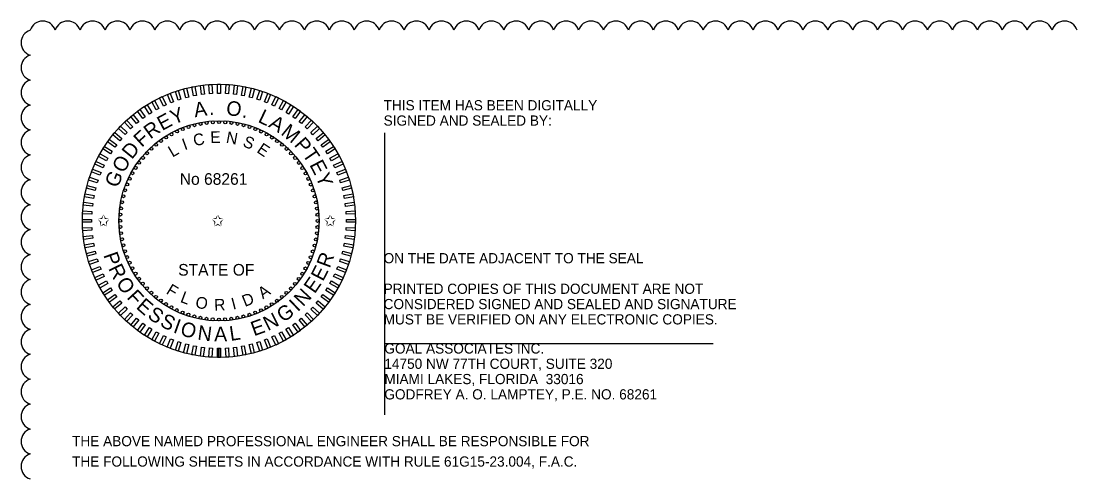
# Model space of a CAD drawing. Extents: x -811 to 10319, y -2309 to 9962.
# Drawn here: x -810.85 to -803.6, y -2238.16 to -2235.02 of the extents above; entities that cross this region are included whole.
import ezdxf

# ---------------------------------------------------------------- set-up
doc = ezdxf.new("R2010")
doc.units = 0
for name, color, linetype in [('AdhocPoint_dp', 7, 'Continuous'), ('PlotBorder_dp', 7, 'Continuous'), ('TextMinor', 7, 'Continuous'), ('TextShtNo', 7, 'Continuous'), ('TextTitle', 7, 'Continuous')]:
    doc.layers.add(name, color=color, linetype=linetype)

msp = doc.modelspace()

# ---------------------------------------------------------------- linework, layer by layer
at = {"layer": 'AdhocPoint_dp'}
for p, q in [((-808.3546, -2235.7843), (-808.3546, -2237.719)), ((-808.3546, -2237.229), (-806.0979, -2237.229))]:
    msp.add_line(p, q, dxfattribs=at)
at = {"layer": 'TextMinor'}
for radius in [0.9375, 0.6875]:
    msp.add_circle((-809.4901, -2236.3877), radius, dxfattribs=at)
at = {"layer": 'TextShtNo'}
for p, q in [((-809.5001, -2237.3253), (-809.5003, -2237.2628)), ((-809.4901, -2237.3252), (-809.4903, -2237.2627)), ((-809.4801, -2237.3252), (-809.4803, -2237.2627))]:
    msp.add_line(p, q, dxfattribs=at)
for points in [[(-809.6441, -2235.5263), (-809.6639, -2235.5301), (-809.6756, -2235.4688), (-809.6558, -2235.465)], [(-809.5897, -2235.5183), (-809.6097, -2235.5209), (-809.6175, -2235.4589), (-809.5975, -2235.4564)], [(-809.5349, -2235.5138), (-809.555, -2235.5151), (-809.559, -2235.4527), (-809.5388, -2235.4515)], [(-809.4799, -2235.5127), (-809.5001, -2235.5127), (-809.5001, -2235.4503), (-809.4799, -2235.4503)], [(-809.425, -2235.5151), (-809.4452, -2235.5138), (-809.4412, -2235.4515), (-809.4211, -2235.4528)], [(-809.3703, -2235.5209), (-809.3904, -2235.5184), (-809.3825, -2235.4564), (-809.3625, -2235.4589)], [(-809.3162, -2235.5301), (-809.336, -2235.5263), (-809.3243, -2235.465), (-809.3045, -2235.4688)], [(-809.8535, -2235.5917), (-809.8717, -2235.6002), (-809.8983, -2235.5438), (-809.8801, -2235.5352)], [(-809.8028, -2235.5704), (-809.8215, -2235.5778), (-809.8445, -2235.5198), (-809.8258, -2235.5124)], [(-809.7508, -2235.5524), (-809.77, -2235.5586), (-809.7893, -2235.4992), (-809.7701, -2235.493)], [(-809.6979, -2235.5377), (-809.7174, -2235.5427), (-809.7329, -2235.4822), (-809.7134, -2235.4772)], [(-809.2626, -2235.5427), (-809.2822, -2235.5377), (-809.2667, -2235.4772), (-809.2471, -2235.4823)], [(-809.21, -2235.5587), (-809.2292, -2235.5524), (-809.2099, -2235.4931), (-809.1907, -2235.4993)], [(-809.1585, -2235.5779), (-809.1773, -2235.5705), (-809.1543, -2235.5124), (-809.1355, -2235.5199)], [(-809.1083, -2235.6003), (-809.1266, -2235.5917), (-809.1, -2235.5352), (-809.0817, -2235.5438)], [(-809.9504, -2235.6435), (-809.9674, -2235.6543), (-810.0009, -2235.6016), (-809.9838, -2235.5908)], [(-809.9027, -2235.616), (-809.9204, -2235.6258), (-809.9505, -2235.571), (-809.9328, -2235.5613)], [(-809.0596, -2235.6259), (-809.0773, -2235.6161), (-809.0473, -2235.5614), (-809.0296, -2235.5711)], [(-809.0127, -2235.6544), (-809.0297, -2235.6436), (-808.9962, -2235.5909), (-808.9792, -2235.6017)], [(-810.04, -2235.707), (-810.0556, -2235.7199), (-810.0954, -2235.6718), (-810.0798, -2235.6589)], [(-809.9962, -2235.6738), (-810.0125, -2235.6857), (-810.0492, -2235.6352), (-810.0329, -2235.6233)], [(-808.9676, -2235.6858), (-808.9839, -2235.674), (-808.9472, -2235.6234), (-808.9308, -2235.6353)], [(-808.9245, -2235.72), (-808.9401, -2235.7071), (-808.9003, -2235.659), (-808.8847, -2235.6719)], [(-810.121, -2235.7813), (-810.1348, -2235.796), (-810.1804, -2235.7533), (-810.1665, -2235.7386)], [(-810.0817, -2235.7429), (-810.0964, -2235.7567), (-810.1392, -2235.7112), (-810.1244, -2235.6974)], [(-808.8837, -2235.7568), (-808.8984, -2235.743), (-808.8557, -2235.6975), (-808.841, -2235.7113)], [(-808.8453, -2235.7962), (-808.8591, -2235.7815), (-808.8136, -2235.7387), (-808.7998, -2235.7534)], [(-810.192, -2235.8652), (-810.2039, -2235.8815), (-810.2544, -2235.8448), (-810.2426, -2235.8285)], [(-810.1579, -2235.8221), (-810.1707, -2235.8377), (-810.2188, -2235.7979), (-810.206, -2235.7823)], [(-808.8094, -2235.8378), (-808.8223, -2235.8223), (-808.7742, -2235.7825), (-808.7613, -2235.798)], [(-808.7762, -2235.8817), (-808.7881, -2235.8653), (-808.7376, -2235.8286), (-808.7257, -2235.845)], [(-810.2235, -2235.9103), (-810.2343, -2235.9273), (-810.287, -2235.8939), (-810.2762, -2235.8768)], [(-808.7459, -2235.9275), (-808.7567, -2235.9104), (-808.7039, -2235.877), (-808.6931, -2235.894)], [(-810.2775, -2236.006), (-810.2861, -2236.0242), (-810.3426, -2235.9976), (-810.334, -2235.9794)], [(-810.252, -2235.9573), (-810.2617, -2235.975), (-810.3164, -2235.9449), (-810.3067, -2235.9272)], [(-808.7184, -2235.9751), (-808.7281, -2235.9574), (-808.6734, -2235.9273), (-808.6637, -2235.945)], [(-808.694, -2236.0244), (-808.7026, -2236.0061), (-808.6461, -2235.9795), (-808.6375, -2235.9978)], [(-810.3, -2236.0562), (-810.3074, -2236.0749), (-810.3654, -2236.0519), (-810.358, -2236.0332)], [(-808.6728, -2236.0751), (-808.6802, -2236.0563), (-808.6222, -2236.0333), (-808.6147, -2236.0521)], [(-810.3192, -2236.1077), (-810.3254, -2236.1269), (-810.3848, -2236.1076), (-810.3786, -2236.0884)], [(-808.6548, -2236.127), (-808.661, -2236.1078), (-808.6016, -2236.0885), (-808.5954, -2236.1077)], [(-810.3351, -2236.1603), (-810.3401, -2236.1798), (-810.4006, -2236.1643), (-810.3956, -2236.1447)], [(-808.64, -2236.18), (-808.6451, -2236.1604), (-808.5846, -2236.1449), (-808.5796, -2236.1645)], [(-810.357, -2236.268), (-810.3595, -2236.288), (-810.4215, -2236.2802), (-810.4189, -2236.2601)], [(-810.3477, -2236.2138), (-810.3515, -2236.2336), (-810.4129, -2236.2219), (-810.4091, -2236.2021)], [(-808.6287, -2236.2338), (-808.6325, -2236.214), (-808.5711, -2236.2023), (-808.5673, -2236.2221)], [(-808.6207, -2236.2882), (-808.6232, -2236.2682), (-808.5613, -2236.2603), (-808.5588, -2236.2804)], [(-810.3628, -2236.3226), (-810.3641, -2236.3428), (-810.4264, -2236.3389), (-810.4251, -2236.3187)], [(-808.6162, -2236.343), (-808.6174, -2236.3228), (-808.5551, -2236.3189), (-808.5539, -2236.339)], [(-810.3652, -2236.3776), (-810.3652, -2236.3977), (-810.4276, -2236.3977), (-810.4276, -2236.3776)], [(-808.6151, -2236.3979), (-808.6151, -2236.3777), (-808.5527, -2236.3777), (-808.5527, -2236.3979)], [(-810.3641, -2236.4325), (-810.3628, -2236.4527), (-810.4251, -2236.4566), (-810.4264, -2236.4364)], [(-810.3595, -2236.4873), (-810.357, -2236.5073), (-810.4189, -2236.5152), (-810.4215, -2236.4951)], [(-808.6233, -2236.5075), (-808.6207, -2236.4875), (-808.5588, -2236.4953), (-808.5613, -2236.5153)], [(-808.6175, -2236.4529), (-808.6162, -2236.4327), (-808.5539, -2236.4366), (-808.5551, -2236.4568)], [(-810.3516, -2236.5417), (-810.3478, -2236.5615), (-810.4091, -2236.5732), (-810.4129, -2236.5534)], [(-808.6325, -2236.5617), (-808.6287, -2236.5419), (-808.5674, -2236.5536), (-808.5712, -2236.5734)], [(-810.3402, -2236.5955), (-810.3352, -2236.615), (-810.3957, -2236.6306), (-810.4007, -2236.611)], [(-808.6451, -2236.6152), (-808.6401, -2236.5957), (-808.5796, -2236.6112), (-808.5846, -2236.6307)], [(-810.3255, -2236.6485), (-810.3192, -2236.6677), (-810.3786, -2236.6869), (-810.3849, -2236.6677)], [(-810.3075, -2236.7004), (-810.3, -2236.7192), (-810.3581, -2236.7421), (-810.3655, -2236.7234)], [(-808.6803, -2236.7193), (-808.6729, -2236.7006), (-808.6148, -2236.7236), (-808.6222, -2236.7423)], [(-808.6611, -2236.6678), (-808.6548, -2236.6486), (-808.5954, -2236.6679), (-808.6017, -2236.6871)], [(-810.2862, -2236.7511), (-810.2776, -2236.7694), (-810.3341, -2236.7959), (-810.3427, -2236.7777)], [(-808.7027, -2236.7695), (-808.6941, -2236.7513), (-808.6376, -2236.7778), (-808.6462, -2236.7961)], [(-810.2618, -2236.8004), (-810.2521, -2236.8181), (-810.3068, -2236.8481), (-810.3165, -2236.8304)], [(-810.2344, -2236.848), (-810.2236, -2236.8651), (-810.2763, -2236.8985), (-810.2871, -2236.8815)], [(-808.7568, -2236.8652), (-808.746, -2236.8482), (-808.6932, -2236.8816), (-808.704, -2236.8987)], [(-808.7282, -2236.8182), (-808.7185, -2236.8005), (-808.6638, -2236.8306), (-808.6735, -2236.8483)], [(-810.204, -2236.8938), (-810.1922, -2236.9102), (-810.2427, -2236.9469), (-810.2545, -2236.9305)], [(-808.7882, -2236.9103), (-808.7763, -2236.894), (-808.7258, -2236.9307), (-808.7377, -2236.947)], [(-810.1708, -2236.9377), (-810.158, -2236.9532), (-810.2061, -2236.993), (-810.2189, -2236.9775)], [(-810.135, -2236.9793), (-810.1211, -2236.994), (-810.1667, -2237.0368), (-810.1805, -2237.0221)], [(-808.8592, -2236.9942), (-808.8454, -2236.9795), (-808.7999, -2237.0222), (-808.8137, -2237.0369)], [(-808.8224, -2236.9534), (-808.8095, -2236.9378), (-808.7614, -2236.9776), (-808.7743, -2236.9932)], [(-810.0965, -2237.0186), (-810.0818, -2237.0325), (-810.1246, -2237.078), (-810.1393, -2237.0642)], [(-810.0557, -2237.0555), (-810.0402, -2237.0683), (-810.08, -2237.1164), (-810.0955, -2237.1036)], [(-808.9402, -2237.0685), (-808.9247, -2237.0556), (-808.8848, -2237.1037), (-808.9004, -2237.1166)], [(-808.8985, -2237.0326), (-808.8838, -2237.0188), (-808.8411, -2237.0643), (-808.8558, -2237.0781)], [(-810.0127, -2237.0897), (-809.9964, -2237.1015), (-810.0331, -2237.152), (-810.0494, -2237.1402)], [(-809.9676, -2237.1211), (-809.9505, -2237.1319), (-809.984, -2237.1846), (-810.001, -2237.1738)], [(-809.0299, -2237.132), (-809.0128, -2237.1212), (-808.9794, -2237.1739), (-808.9964, -2237.1847)], [(-808.984, -2237.1016), (-808.9677, -2237.0898), (-808.931, -2237.1403), (-808.9473, -2237.1522)], [(-809.9206, -2237.1496), (-809.9029, -2237.1594), (-809.933, -2237.2141), (-809.9507, -2237.2043)], [(-809.8719, -2237.1752), (-809.8536, -2237.1838), (-809.8802, -2237.2402), (-809.8985, -2237.2317)], [(-809.8217, -2237.1976), (-809.8029, -2237.205), (-809.8259, -2237.2631), (-809.8447, -2237.2556)], [(-809.1775, -2237.2051), (-809.1587, -2237.1976), (-809.1357, -2237.2557), (-809.1545, -2237.2631)], [(-809.1268, -2237.1838), (-809.1085, -2237.1752), (-809.0819, -2237.2317), (-809.1002, -2237.2403)], [(-809.0775, -2237.1594), (-809.0598, -2237.1497), (-809.0297, -2237.2044), (-809.0474, -2237.2142)], [(-809.7702, -2237.2168), (-809.751, -2237.223), (-809.7703, -2237.2824), (-809.7895, -2237.2762)], [(-809.7176, -2237.2327), (-809.698, -2237.2378), (-809.7136, -2237.2982), (-809.7331, -2237.2932)], [(-809.6641, -2237.2454), (-809.6443, -2237.2491), (-809.656, -2237.3105), (-809.6758, -2237.3067)], [(-809.6099, -2237.2546), (-809.5899, -2237.2571), (-809.5977, -2237.3191), (-809.6177, -2237.3165)], [(-809.5552, -2237.2604), (-809.5351, -2237.2617), (-809.539, -2237.324), (-809.5592, -2237.3227)], [(-809.5003, -2237.2628), (-809.4801, -2237.2628), (-809.4801, -2237.3252), (-809.5003, -2237.3252)], [(-809.4453, -2237.2617), (-809.4252, -2237.2604), (-809.4213, -2237.3227), (-809.4414, -2237.324)], [(-809.3906, -2237.2571), (-809.3705, -2237.2546), (-809.3627, -2237.3166), (-809.3827, -2237.3191)], [(-809.3362, -2237.2492), (-809.3163, -2237.2454), (-809.3046, -2237.3067), (-809.3245, -2237.3105)], [(-809.2824, -2237.2378), (-809.2628, -2237.2328), (-809.2473, -2237.2933), (-809.2668, -2237.2983)], [(-809.2294, -2237.2231), (-809.2102, -2237.2169), (-809.1909, -2237.2762), (-809.2101, -2237.2825)]]:
    msp.add_lwpolyline(points, close=True, dxfattribs=at)
for centre in [(-809.7781, -2235.7745), (-809.739, -2235.7576), (-809.6989, -2235.7433), (-809.6581, -2235.7314), (-809.6165, -2235.7222), (-809.5745, -2235.7155), (-809.5321, -2235.7116), (-809.4896, -2235.7103), (-809.447, -2235.7116), (-809.4047, -2235.7157), (-809.3626, -2235.7224), (-809.3211, -2235.7317), (-809.2802, -2235.7436), (-809.2402, -2235.7581), (-809.2012, -2235.775), (-809.8879, -2235.8393), (-809.8527, -2235.8154), (-809.816, -2235.7938), (-809.1633, -2235.7943), (-809.1266, -2235.816), (-809.0915, -2235.84), (-809.9535, -2235.8935), (-809.9215, -2235.8654), (-809.0579, -2235.8661), (-809.026, -2235.8943), (-810.0379, -2235.9891), (-810.0118, -2235.9555), (-809.9836, -2235.9236), (-808.9959, -2235.9244), (-808.9678, -2235.9563), (-808.9417, -2235.99), (-810.0835, -2236.0609), (-810.0618, -2236.0243), (-808.9178, -2236.0252), (-808.8962, -2236.0619), (-810.1029, -2236.0988), (-808.8769, -2236.0998), (-810.1343, -2236.1779), (-810.1198, -2236.1378), (-808.86, -2236.1389), (-808.8456, -2236.1789), (-810.1555, -2236.2602), (-810.1462, -2236.2187), (-808.8338, -2236.2198), (-808.8245, -2236.2614), (-810.1662, -2236.3446), (-810.1622, -2236.3023), (-808.8179, -2236.3034), (-808.814, -2236.3458), (-810.1676, -2236.3872), (-808.8127, -2236.3883), (-810.1663, -2236.4297), (-810.1623, -2236.4721), (-808.8181, -2236.4732), (-808.814, -2236.4308), (-810.1557, -2236.5141), (-810.1464, -2236.5557), (-808.8341, -2236.5568), (-808.8248, -2236.5152), (-810.1346, -2236.5966), (-810.1202, -2236.6366), (-808.8604, -2236.6377), (-808.846, -2236.5976), (-810.1034, -2236.6757), (-810.0841, -2236.7136), (-808.8967, -2236.7146), (-808.8774, -2236.6767), (-810.0624, -2236.7503), (-810.0385, -2236.7855), (-808.9424, -2236.7864), (-808.9184, -2236.7512), (-810.0125, -2236.8191), (-809.9844, -2236.8511), (-808.9967, -2236.8519), (-808.9685, -2236.82), (-809.9543, -2236.8812), (-809.9224, -2236.9094), (-809.0587, -2236.9101), (-809.0268, -2236.882), (-809.8888, -2236.9355), (-809.8536, -2236.9594), (-809.817, -2236.9811), (-809.7791, -2237.0005), (-809.2022, -2237.001), (-809.1642, -2236.9817), (-809.1276, -2236.96), (-809.0924, -2236.9362), (-809.74, -2237.0174), (-809.7, -2237.0319), (-809.6591, -2237.0438), (-809.6176, -2237.0531), (-809.5756, -2237.0598), (-809.5332, -2237.0638), (-809.4901, -2237.0652), (-809.4481, -2237.0639), (-809.4058, -2237.0599), (-809.3637, -2237.0533), (-809.3222, -2237.0441), (-809.2813, -2237.0322), (-809.2413, -2237.0178)]:
    msp.add_circle(centre, 0.01, dxfattribs=at)
at = {"layer": 'TextTitle'}
for centre, start, end in [((-810.7002, -2235.1062), 17.5, 162.5), ((-810.5291, -2235.1062), 17.5, 162.5), ((-810.358, -2235.1062), 17.5, 162.5), ((-810.1868, -2235.1062), 17.5, 162.5), ((-810.0157, -2235.1062), 17.5, 162.5), ((-809.8446, -2235.1062), 17.5, 162.5), ((-809.6735, -2235.1062), 17.5, 162.5), ((-809.5024, -2235.1062), 17.5, 162.5), ((-809.3312, -2235.1062), 17.5, 162.5), ((-809.1601, -2235.1062), 17.5, 162.5), ((-808.989, -2235.1062), 17.5, 162.5), ((-808.8179, -2235.1062), 17.5, 162.5), ((-808.6467, -2235.1062), 17.5, 162.5), ((-808.4756, -2235.1062), 17.5, 162.5), ((-808.3045, -2235.1062), 17.5, 162.5), ((-808.1334, -2235.1062), 17.5, 162.5), ((-807.9622, -2235.1062), 17.5, 162.5), ((-807.7911, -2235.1062), 17.5, 162.5), ((-807.62, -2235.1062), 17.5, 162.5), ((-807.4489, -2235.1062), 17.5, 162.5), ((-807.2778, -2235.1062), 17.5, 162.5), ((-807.1066, -2235.1062), 17.5, 162.5), ((-806.9355, -2235.1062), 17.5, 162.5), ((-806.7644, -2235.1062), 17.5, 162.5), ((-806.5933, -2235.1062), 17.5, 162.5), ((-806.4221, -2235.1062), 17.5, 162.5), ((-806.251, -2235.1062), 17.5, 162.5), ((-806.0799, -2235.1062), 17.5, 162.5), ((-805.9088, -2235.1062), 17.5, 162.5), ((-805.7377, -2235.1062), 17.5, 162.5), ((-805.5665, -2235.1062), 17.5, 162.5), ((-805.3954, -2235.1062), 17.5, 162.5), ((-805.2243, -2235.1062), 17.5, 162.5), ((-805.0532, -2235.1062), 17.5, 162.5), ((-804.882, -2235.1062), 17.5, 162.5), ((-804.7109, -2235.1062), 17.5, 162.5), ((-804.5398, -2235.1062), 17.5, 162.5), ((-804.3687, -2235.1062), 17.5, 162.5), ((-804.1976, -2235.1062), 17.5, 162.5), ((-804.0264, -2235.1062), 17.5, 162.5), ((-803.8553, -2235.1062), 17.5, 162.5), ((-803.6842, -2235.1062), 17.5, 162.5), ((-810.7588, -2235.1648), 107.5, 252.5), ((-810.7588, -2235.3359), 107.5, 252.5), ((-810.7588, -2235.507), 107.5, 252.5), ((-810.7588, -2235.6782), 107.5, 252.5), ((-810.7588, -2235.8493), 107.5, 252.5), ((-810.7588, -2236.0204), 107.5, 252.5), ((-810.7588, -2236.1915), 107.5, 252.5), ((-810.7588, -2236.3627), 107.5, 252.5), ((-810.7588, -2236.5338), 107.5, 252.5), ((-810.7588, -2236.7049), 107.5, 252.5), ((-810.7588, -2236.876), 107.5, 252.5), ((-810.7588, -2237.0471), 107.5, 252.5), ((-810.7588, -2237.2183), 107.5, 252.5), ((-810.7588, -2237.3894), 107.5, 252.5), ((-810.7588, -2237.5605), 107.5, 252.5), ((-810.7588, -2237.7316), 107.5, 252.5), ((-810.7588, -2237.9028), 107.5, 252.5), ((-810.7588, -2238.0739), 107.5, 252.5)]:
    msp.add_arc(centre, 0.0897, start, end, dxfattribs=at)

# ---------------------------------------------------------------- texts
at = {"layer": 'PlotBorder_dp'}
for s, p in [('THIS ITEM HAS BEEN DIGITALLY', (-808.3596, -2235.6292)), ('SIGNED AND SEALED BY:', (-808.3596, -2235.7342)), ('ON THE DATE ADJACENT TO THE SEAL', (-808.3596, -2236.6792)), ('PRINTED COPIES OF THIS DOCUMENT ARE NOT ', (-808.3596, -2236.8892)), ('CONSIDERED SIGNED AND SEALED AND SIGNATURE ', (-808.3596, -2236.9942)), ('MUST BE VERIFIED ON ANY ELECTRONIC COPIES.', (-808.3596, -2237.0992)), ('GOAL ASSOCIATES INC.', (-808.3546, -2237.299)), ('14750 NW 77TH COURT, SUITE 320', (-808.3546, -2237.404)), ('MIAMI LAKES, FLORIDA  33016', (-808.3546, -2237.509)), ('GODFREY A. O. LAMPTEY, P.E. NO. 68261', (-808.3546, -2237.614)), ('THE ABOVE NAMED PROFESSIONAL ENGINEER SHALL BE RESPONSIBLE FOR ', (-810.4987, -2237.9352)), ('THE FOLLOWING SHEETS IN ACCORDANCE WITH RULE 61G15-23.004, F.A.C.', (-810.4987, -2238.0752))]:
    msp.add_text(s, height=0.07, dxfattribs=at).set_placement(p)
at = {"layer": 'TextShtNo'}
for s, height, rotation, p in [('Y', 0.1, 21.06329, (-809.8021, -2235.7283)), ('A', 0.1, 8.80884, (-809.6551, -2235.6771)), ('O', 0.1, 352.18771, (-809.4449, -2235.6596)), ('E', 0.1, 28.10553, (-809.8806, -2235.7716)), ('.', 0.1, 1.04184, (-809.5575, -2235.6613)), ('.', 0.1, 343.52684, (-809.3358, -2235.6747)), ('L', 0.1, 334.67271, (-809.2279, -2235.707)), ('A', 0.1, 328.40959, (-809.1552, -2235.7397)), ('F', 0.1, 42.37723, (-810.0205, -2235.8868)), ('R', 0.1, 35.92688, (-809.9609, -2235.8304)), ('M', 0.1, 320.6426, (-809.0707, -2235.7909)), ('I', 0.08, 20.01168, (-809.7258, -2235.9037)), ('C', 0.08, 12.20255, (-809.6579, -2235.8761)), ('E', 0.08, 0.41861, (-809.5498, -2235.8527)), ('N', 0.08, 349.29143, (-809.4455, -2235.8512)), ('S', 0.08, 337.02207, (-809.3325, -2235.8729)), ('P', 0.1, 311.19658, (-808.9784, -2235.8678)), ('D', 0.1, 50.8569, (-810.0886, -2235.9705)), ('L', 0.08, 30.40215, (-809.8093, -2235.9541)), ('E', 0.08, 325.86633, (-809.2358, -2235.9132)), ('T', 0.1, 304.45632, (-808.9209, -2235.9315)), ('O', 0.1, 59.51777, (-810.1446, -2236.0654)), ('E', 0.1, 297.63152, (-808.8707, -2236.0023)), ('G', 0.1, 68.0518, (-810.1851, -2236.1661)), ('Y', 0.1, 290.58928, (-808.8281, -2236.0812)), ('P', 0.1, 289.40551, (-810.2848, -2236.6223)), ('R', 0.1, 69.5134, (-808.7299, -2236.7174)), ('R', 0.1, 296.14576, (-810.2518, -2236.714)), ('E', 0.1, 62.47116, (-808.7761, -2236.8082)), ('O', 0.1, 303.96711, (-810.2003, -2236.8146)), ('E', 0.1, 55.42892, (-808.833, -2236.8925)), ('F', 0.08, 328.72408, (-809.8582, -2236.8843)), ('A', 0.08, 34.49917, (-809.1883, -2236.9271)), ('N', 0.1, 47.17876, (-808.9123, -2236.9816)), ('F', 0.1, 312.62798, (-810.1279, -2236.9167)), ('E', 0.1, 319.07833, (-810.0645, -2236.985)), ('L', 0.08, 339.29159, (-809.7609, -2236.9434)), ('O', 0.08, 349.68206, (-809.6562, -2236.9831)), ('R', 0.08, 2.33977, (-809.5217, -2237.005)), ('I', 0.08, 14.20366, (-809.3941, -2236.9984)), ('D', 0.08, 22.01279, (-809.312, -2236.9796)), ('S', 0.1, 326.12056, (-809.9869, -2237.0509)), ('G', 0.1, 35.11153, (-809.0492, -2237.0893)), ('I', 0.1, 43.64556, (-808.9499, -2237.0161)), ('S', 0.1, 333.193, (-809.9015, -2237.107)), ('I', 0.1, 340.26543, (-809.8098, -2237.1522)), ('E', 0.1, 19.81912, (-809.2498, -2237.1807)), ('N', 0.1, 26.86136, (-809.1544, -2237.1453)), ('O', 0.1, 343.79863, (-809.7621, -2237.1704)), ('N', 0.1, 352.45949, (-809.6411, -2237.2025)), ('A', 0.1, 0.70966, (-809.5227, -2237.2157)), ('L', 0.1, 8.47665, (-809.4105, -2237.2125))]:
    msp.add_text(s, height=height, rotation=rotation, dxfattribs=at).set_placement(p)
for s, p in [('No 68261', (-809.7591, -2236.1405)), ('✩', (-810.3251, -2236.4257)), ('✩', (-809.5404, -2236.4257)), ('✩', (-808.7685, -2236.4257)), ('STATE OF', (-809.7698, -2236.7639))]:
    msp.add_text(s, height=0.08, dxfattribs=at).set_placement(p)

doc.saveas('drawing.dxf')
